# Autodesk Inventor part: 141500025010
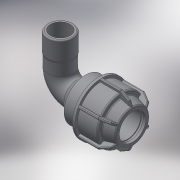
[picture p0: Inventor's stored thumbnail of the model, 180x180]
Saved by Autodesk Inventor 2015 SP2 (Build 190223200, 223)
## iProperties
Created: 2017-08
Part Number: 141500025010
Material: Generic
Description: L.14 90° ELBOW FEMALE ADAPTOR (SILVER) 25-1"
Document SubType Name: Modeling
Designer: KIM
Density: 1 g/cm^3
Appearance: Default
Author: KIM
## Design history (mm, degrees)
derived "141500.ipt"
feature "Solid1::141500.ipt"
feature "Solid2::141500.ipt"
tag "TaggingFeature1"
body "Solid1"
body "Solid2"
other parameters: "d1" = 25, "d2" = 48, "d4" = 15 deg, "d5" = 31.68, "d6" = 10.4544, "d16" = 25.5, "d17" = 2.4, "d24" = 2.4, "d25" = 45, "d26" = 37.5, "d27" = 2.4, "d28" = 135 deg, "d29" = 1.44, "d31" = 1.25, "d46" = 150 deg, "d49" = 2.5, "d50" = 0, "d58" = 0.75, "d61" = 360 deg, "d63" = 22.5, "d95" = 30.291, "d96" = 39.3783, "d97" = 21, "d98" = 24.2328, "d99" = 35.44047, "d100" = 135 deg, "d108" = 1.25, "d112" = 27.3, "d113" = 68, "d114" = 48.96, "d115" = 35.44047, "d116" = 45 deg, "d117" = 0, "d118" = 0, "d_" = 25, "G_" = 30.291, "A_" = 68, "l_" = 48, "l_2" = 21
